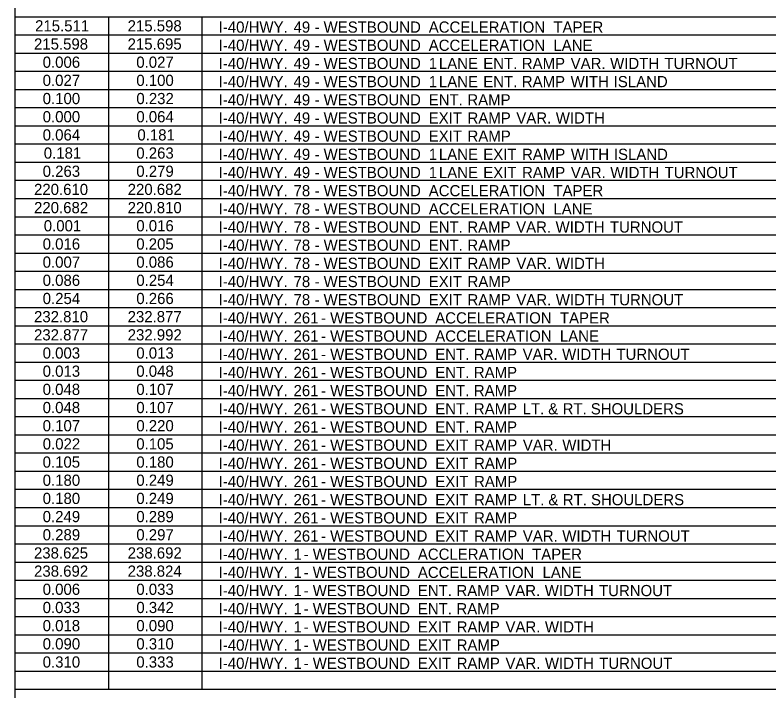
# Model space of a CAD drawing. Extents: x 2261867 to 2275370, y -3124789 to -3122260.
# Drawn here: x 2269400.2 to 2269764, y -3124228.5 to -3123902.3 of the extents above; entities that cross this region are included whole.
import ezdxf

# ---------------------------------------------------------------- set-up
doc = ezdxf.new("R2010")
doc.units = 0
doc.layers.add('Default', color=7, linetype='Continuous')

msp = doc.modelspace()

# ---------------------------------------------------------------- linework, layer by layer
at = {"layer": 'Default'}
for p, q in [((2269400.16, -3124701.59), (2269400.16, -3123657.37)), ((2269400.16, -3124701.59), (2269400.16, -3123657.37)), ((2269400.16, -3123903.07), (2270414.11, -3123903.07)), ((2269445.35, -3124218.97), (2269445.35, -3123903.07)), ((2269445.35, -3124227.74), (2269445.35, -3123903.07)), ((2269490.54, -3124210.19), (2269490.54, -3123903.07)), ((2269490.54, -3124227.74), (2269490.54, -3123903.07)), ((2269400.16, -3123911.84), (2270414.11, -3123911.84)), ((2269400.16, -3123920.62), (2270414.11, -3123920.62)), ((2269400.16, -3123929.39), (2270414.11, -3123929.39)), ((2269400.16, -3123938.17), (2270414.11, -3123938.17)), ((2269400.16, -3123946.94), (2270414.11, -3123946.94)), ((2269400.16, -3123955.72), (2270414.11, -3123955.72)), ((2269400.16, -3123964.49), (2270414.11, -3123964.49)), ((2269400.16, -3123973.27), (2270414.11, -3123973.27)), ((2269400.16, -3123982.04), (2270414.11, -3123982.04)), ((2269400.16, -3123990.82), (2270414.11, -3123990.82)), ((2269400.16, -3123999.59), (2270414.11, -3123999.59)), ((2269400.16, -3124008.37), (2270414.11, -3124008.37)), ((2269400.16, -3124017.14), (2270414.11, -3124017.14)), ((2269400.16, -3124025.92), (2270414.11, -3124025.92)), ((2269400.16, -3124034.69), (2270414.11, -3124034.69)), ((2269400.16, -3124043.47), (2270414.11, -3124043.47)), ((2269400.16, -3124052.24), (2270414.11, -3124052.24)), ((2269400.16, -3124061.02), (2270414.11, -3124061.02)), ((2269400.16, -3124069.79), (2270414.11, -3124069.79)), ((2269400.16, -3124078.57), (2270414.11, -3124078.57)), ((2269400.16, -3124087.34), (2270414.11, -3124087.34)), ((2269400.16, -3124096.12), (2270414.11, -3124096.12)), ((2269400.16, -3124104.89), (2270414.11, -3124104.89)), ((2269400.16, -3124113.67), (2270414.11, -3124113.67)), ((2269400.16, -3124122.44), (2270414.11, -3124122.44)), ((2269400.16, -3124131.22), (2270414.11, -3124131.22)), ((2269400.16, -3124139.99), (2270414.11, -3124139.99)), ((2269400.16, -3124148.77), (2270414.11, -3124148.77)), ((2269400.16, -3124157.54), (2270414.11, -3124157.54)), ((2269400.16, -3124166.32), (2270414.11, -3124166.32)), ((2269400.16, -3124175.09), (2270414.11, -3124175.09)), ((2269400.16, -3124183.87), (2270414.11, -3124183.87)), ((2269400.16, -3124192.64), (2270414.11, -3124192.64)), ((2269400.16, -3124201.42), (2270414.11, -3124201.42)), ((2269400.16, -3124210.19), (2270414.11, -3124210.19)), ((2269400.16, -3124218.97), (2269859.53, -3124218.97)), ((2269490.54, -3124227.74), (2269490.54, -3124218.97)), ((2269400.16, -3124227.74), (2270414.11, -3124227.74)), ((2269490.54, -3124227.74), (2269769.15, -3124227.74))]:
    msp.add_line(p, q, dxfattribs=at)

# ---------------------------------------------------------------- texts
for s, p in [('215.511', (2269409.82, -3123910.16)), ('215.598', (2269454.49, -3123910.16)), ('I-40/HWY.', (2269498.44, -3123910.76)), (' 49', (2269532.57, -3123910.76)), (' WESTBOUND', (2269547.09, -3123910.76)), (' ACCELERATION', (2269597.83, -3123910.76)), (' TAPER', (2269658.01, -3123910.76)), (' -', (2269542.72, -3123910.76)), ('215.598', (2269409.29, -3123918.93)), ('215.695', (2269454.47, -3123918.93)), ('I-40/HWY.', (2269498.44, -3123919.54)), (' 49', (2269532.57, -3123919.54)), (' WESTBOUND', (2269547.09, -3123919.54)), (' ACCELERATION', (2269597.83, -3123919.54)), (' LANE', (2269658.01, -3123919.54)), (' -', (2269542.72, -3123919.54)), ('0.006', (2269413.49, -3123927.71)), ('0.027', (2269458.68, -3123927.71)), ('I-40/HWY.', (2269498.44, -3123928.31)), (' 49', (2269532.57, -3123928.31)), (' -', (2269542.72, -3123928.31)), (' WESTBOUND', (2269547.09, -3123928.31)), (' 1', (2269597.83, -3123928.31)), (' LANE', (2269602.73, -3123928.31)), (' ENT.', (2269624.14, -3123928.31)), (' RAMP', (2269642.76, -3123928.31)), (' VAR.', (2269666.33, -3123928.31)), (' WIDTH', (2269685.38, -3123928.31)), (' TURNOUT', (2269711.59, -3123928.31)), ('0.027', (2269413.49, -3123936.48)), ('0.100', (2269458.69, -3123936.48)), ('I-40/HWY.', (2269498.44, -3123937.09)), (' 49', (2269532.57, -3123937.09)), (' WESTBOUND', (2269547.09, -3123937.09)), (' 1', (2269597.83, -3123937.09)), (' LANE', (2269602.73, -3123937.09)), (' ENT.', (2269624.14, -3123937.09)), (' RAMP', (2269642.76, -3123937.09)), (' WITH', (2269666.33, -3123937.09)), (' ISLAND', (2269687.09, -3123937.09)), (' -', (2269542.72, -3123937.09)), ('0.100', (2269413.5, -3123945.26)), ('0.232', (2269458.71, -3123945.26)), ('I-40/HWY.', (2269498.44, -3123945.86)), (' 49', (2269532.57, -3123945.86)), (' WESTBOUND', (2269547.09, -3123945.86)), (' ENT.', (2269597.83, -3123945.86)), (' RAMP', (2269616.46, -3123945.86)), (' -', (2269542.72, -3123945.86)), ('0.000', (2269413.5, -3123954.03)), ('0.064', (2269458.7, -3123954.03)), ('I-40/HWY.', (2269498.44, -3123954.64)), (' 49', (2269532.57, -3123954.64)), (' WESTBOUND', (2269547.09, -3123954.64)), (' EXIT', (2269597.83, -3123954.64)), (' RAMP', (2269616.55, -3123954.64)), (' VAR.', (2269640.11, -3123954.64)), (' WIDTH', (2269659.16, -3123954.64)), (' -', (2269542.72, -3123954.64)), ('0.064', (2269413.5, -3123962.81)), ('0.181', (2269459.21, -3123962.81)), ('I-40/HWY.', (2269498.44, -3123963.41)), (' 49', (2269532.57, -3123963.41)), (' WESTBOUND', (2269547.09, -3123963.41)), (' EXIT', (2269597.83, -3123963.41)), (' RAMP', (2269616.55, -3123963.41)), (' -', (2269542.72, -3123963.41)), ('0.181', (2269414.02, -3123971.58)), ('0.263', (2269458.68, -3123971.58)), ('I-40/HWY.', (2269498.44, -3123972.19)), (' 49', (2269532.57, -3123972.19)), (' WESTBOUND', (2269547.09, -3123972.19)), (' 1', (2269597.83, -3123972.19)), (' LANE', (2269602.73, -3123972.19)), (' EXIT', (2269624.14, -3123972.19)), (' RAMP', (2269642.85, -3123972.19)), (' WITH', (2269666.42, -3123972.19)), (' ISLAND', (2269687.18, -3123972.19)), (' -', (2269542.72, -3123972.19)), ('0.263', (2269413.49, -3123980.36)), ('0.279', (2269458.68, -3123980.36)), ('I-40/HWY.', (2269498.44, -3123980.96)), (' 49', (2269532.57, -3123980.96)), (' WESTBOUND', (2269547.09, -3123980.96)), (' 1', (2269597.83, -3123980.96)), (' LANE', (2269602.73, -3123980.96)), (' EXIT', (2269624.14, -3123980.96)), (' RAMP', (2269642.85, -3123980.96)), (' VAR.', (2269666.42, -3123980.96)), (' WIDTH', (2269685.47, -3123980.96)), (' TURNOUT', (2269711.68, -3123980.96)), (' -', (2269542.72, -3123980.96)), ('220.610', (2269409.31, -3123989.13)), ('220.682', (2269454.52, -3123989.13)), ('I-40/HWY.', (2269498.44, -3123989.74)), (' 78', (2269532.57, -3123989.74)), (' WESTBOUND', (2269547.09, -3123989.74)), (' ACCELERATION', (2269597.83, -3123989.74)), (' -', (2269542.72, -3123989.74)), (' TAPER', (2269658.01, -3123989.74)), ('220.682', (2269409.33, -3123997.91)), ('220.810', (2269454.5, -3123997.91)), ('I-40/HWY.', (2269498.44, -3123998.51)), (' 78', (2269532.57, -3123998.51)), (' WESTBOUND', (2269547.09, -3123998.51)), (' ACCELERATION', (2269597.83, -3123998.51)), (' LANE', (2269658.01, -3123998.51)), (' -', (2269542.72, -3123998.51)), ('0.001', (2269414.02, -3124006.68)), ('0.016', (2269458.68, -3124006.68)), ('I-40/HWY.', (2269498.44, -3124007.29)), (' 78', (2269532.57, -3124007.29)), (' WESTBOUND', (2269547.09, -3124007.29)), (' ENT.', (2269597.83, -3124007.29)), (' RAMP', (2269616.46, -3124007.29)), (' VAR.', (2269640.02, -3124007.29)), (' WIDTH', (2269659.07, -3124007.29)), (' TURNOUT', (2269685.28, -3124007.29)), (' -', (2269542.72, -3124007.29)), ('0.016', (2269413.49, -3124015.46)), ('0.205', (2269458.66, -3124015.46)), ('I-40/HWY.', (2269498.44, -3124016.06)), (' 78', (2269532.57, -3124016.06)), (' WESTBOUND', (2269547.09, -3124016.06)), (' ENT.', (2269597.83, -3124016.06)), (' RAMP', (2269616.46, -3124016.06)), (' -', (2269542.72, -3124016.06)), ('0.007', (2269413.49, -3124024.23)), ('0.086', (2269458.68, -3124024.23)), ('I-40/HWY.', (2269498.44, -3124024.84)), (' 78', (2269532.57, -3124024.84)), (' WESTBOUND', (2269547.09, -3124024.84)), (' EXIT', (2269597.83, -3124024.84)), (' RAMP', (2269616.55, -3124024.84)), (' VAR.', (2269640.11, -3124024.84)), (' WIDTH', (2269659.16, -3124024.84)), (' -', (2269542.72, -3124024.84)), ('0.086', (2269413.49, -3124033.01)), ('0.254', (2269458.7, -3124033.01)), ('I-40/HWY.', (2269498.44, -3124033.61)), (' 78', (2269532.57, -3124033.61)), (' -', (2269542.72, -3124033.61)), (' WESTBOUND', (2269547.09, -3124033.61)), (' EXIT', (2269597.83, -3124033.61)), (' RAMP', (2269616.55, -3124033.61)), ('0.254', (2269413.5, -3124041.78)), ('0.266', (2269458.68, -3124041.78)), ('I-40/HWY.', (2269498.44, -3124042.39)), (' 78', (2269532.57, -3124042.39)), (' WESTBOUND', (2269547.09, -3124042.39)), (' EXIT', (2269597.83, -3124042.39)), (' RAMP', (2269616.55, -3124042.39)), (' VAR.', (2269640.11, -3124042.39)), (' WIDTH', (2269659.16, -3124042.39)), (' TURNOUT', (2269685.37, -3124042.39)), (' -', (2269542.72, -3124042.39)), ('232.810', (2269409.31, -3124050.56)), ('232.877', (2269454.49, -3124050.56)), ('I-40/HWY.', (2269498.44, -3124051.16)), (' 261', (2269532.57, -3124051.16)), (' WESTBOUND', (2269550.23, -3124051.16)), (' ACCELERATION', (2269600.97, -3124051.16)), (' TAPER', (2269661.15, -3124051.16)), (' -', (2269545.86, -3124051.16)), ('232.877', (2269409.3, -3124059.33)), ('232.992', (2269454.52, -3124059.33)), ('I-40/HWY.', (2269498.44, -3124059.94)), (' 261', (2269532.57, -3124059.94)), (' WESTBOUND', (2269550.23, -3124059.94)), (' ACCELERATION', (2269600.97, -3124059.94)), (' LANE', (2269661.15, -3124059.94)), (' -', (2269545.86, -3124059.94)), ('0.003', (2269413.49, -3124068.11)), ('0.013', (2269458.68, -3124068.11)), ('I-40/HWY.', (2269498.44, -3124068.71)), (' 261', (2269532.57, -3124068.71)), (' WESTBOUND', (2269550.23, -3124068.71)), (' ENT.', (2269600.97, -3124068.71)), (' RAMP', (2269619.6, -3124068.71)), (' VAR.', (2269643.16, -3124068.71)), (' WIDTH', (2269662.21, -3124068.71)), (' TURNOUT', (2269688.42, -3124068.71)), (' -', (2269545.86, -3124068.71)), ('0.013', (2269413.49, -3124076.88)), ('0.048', (2269458.68, -3124076.88)), ('I-40/HWY.', (2269498.44, -3124077.49)), (' 261', (2269532.57, -3124077.49)), (' -', (2269545.86, -3124077.49)), (' WESTBOUND', (2269550.23, -3124077.49)), (' ENT.', (2269600.97, -3124077.49)), (' RAMP', (2269619.6, -3124077.49)), ('0.048', (2269413.49, -3124085.66)), ('0.107', (2269458.68, -3124085.66)), ('I-40/HWY.', (2269498.44, -3124086.26)), (' 261', (2269532.57, -3124086.26)), (' WESTBOUND', (2269550.23, -3124086.26)), (' ENT.', (2269600.97, -3124086.26)), (' RAMP', (2269619.6, -3124086.26)), (' -', (2269545.86, -3124086.26)), ('0.048', (2269413.49, -3124094.43)), ('0.107', (2269458.68, -3124094.43)), ('I-40/HWY.', (2269498.44, -3124095.04)), (' 261', (2269532.57, -3124095.04)), (' WESTBOUND', (2269550.23, -3124095.04)), (' ENT.', (2269600.97, -3124095.04)), (' RAMP', (2269619.6, -3124095.04)), (' LT.', (2269643.16, -3124095.04)), (' &', (2269655.5, -3124095.04)), (' RT.', (2269662.45, -3124095.04)), (' SHOULDERS', (2269676.04, -3124095.04)), (' -', (2269545.86, -3124095.04)), ('0.107', (2269413.49, -3124103.21)), ('0.220', (2269458.69, -3124103.21)), ('I-40/HWY.', (2269498.44, -3124103.81)), (' 261', (2269532.57, -3124103.81)), (' WESTBOUND', (2269550.23, -3124103.81)), (' ENT.', (2269600.97, -3124103.81)), (' RAMP', (2269619.6, -3124103.81)), (' -', (2269545.86, -3124103.81)), ('0.022', (2269413.52, -3124111.98)), ('0.105', (2269458.66, -3124111.98)), ('I-40/HWY.', (2269498.44, -3124112.59)), (' 261', (2269532.57, -3124112.59)), (' WESTBOUND', (2269550.23, -3124112.59)), (' EXIT', (2269600.97, -3124112.59)), (' RAMP', (2269619.69, -3124112.59)), (' VAR.', (2269643.25, -3124112.59)), (' WIDTH', (2269662.3, -3124112.59)), (' -', (2269545.86, -3124112.59)), ('0.105', (2269413.47, -3124120.76)), ('0.180', (2269458.69, -3124120.76)), ('I-40/HWY.', (2269498.44, -3124121.36)), (' 261', (2269532.57, -3124121.36)), (' WESTBOUND', (2269550.23, -3124121.36)), (' EXIT', (2269600.97, -3124121.36)), (' RAMP', (2269619.69, -3124121.36)), (' -', (2269545.86, -3124121.36)), ('0.180', (2269413.5, -3124129.53)), ('0.249', (2269458.68, -3124129.53)), ('I-40/HWY.', (2269498.44, -3124130.14)), (' 261', (2269532.57, -3124130.14)), (' WESTBOUND', (2269550.23, -3124130.14)), (' EXIT', (2269600.97, -3124130.14)), (' RAMP', (2269619.69, -3124130.14)), (' -', (2269545.86, -3124130.14)), ('0.180', (2269413.5, -3124138.31)), ('0.249', (2269458.68, -3124138.31)), ('I-40/HWY.', (2269498.44, -3124138.91)), (' 261', (2269532.57, -3124138.91)), (' WESTBOUND', (2269550.23, -3124138.91)), (' EXIT', (2269600.97, -3124138.91)), (' RAMP', (2269619.69, -3124138.91)), (' LT.', (2269643.25, -3124138.91)), (' &', (2269655.59, -3124138.91)), (' RT.', (2269662.54, -3124138.91)), (' SHOULDERS', (2269676.14, -3124138.91)), (' -', (2269545.86, -3124138.91)), ('0.249', (2269413.49, -3124147.08)), ('0.289', (2269458.68, -3124147.08)), ('I-40/HWY.', (2269498.44, -3124147.69)), (' 261', (2269532.57, -3124147.69)), (' WESTBOUND', (2269550.23, -3124147.69)), (' EXIT', (2269600.97, -3124147.69)), (' RAMP', (2269619.69, -3124147.69)), (' -', (2269545.86, -3124147.69)), ('0.289', (2269413.49, -3124155.86)), ('0.297', (2269458.68, -3124155.86)), ('I-40/HWY.', (2269498.44, -3124156.46)), (' 261', (2269532.57, -3124156.46)), (' WESTBOUND', (2269550.23, -3124156.46)), (' EXIT', (2269600.97, -3124156.46)), (' RAMP', (2269619.69, -3124156.46)), (' VAR.', (2269643.25, -3124156.46)), (' WIDTH', (2269662.3, -3124156.46)), (' TURNOUT', (2269688.51, -3124156.46)), (' -', (2269545.86, -3124156.46)), ('238.625', (2269409.28, -3124164.63)), ('238.692', (2269454.52, -3124164.63)), ('I-40/HWY.', (2269498.44, -3124165.24)), (' 1', (2269532.57, -3124165.24)), (' WESTBOUND', (2269541.84, -3124165.24)), (' ACCLERATION', (2269592.58, -3124165.24)), (' TAPER', (2269647.73, -3124165.24)), (' -', (2269537.47, -3124165.24)), ('238.692', (2269409.33, -3124173.41)), ('238.824', (2269454.5, -3124173.41)), ('I-40/HWY.', (2269498.44, -3124174.01)), (' 1', (2269532.57, -3124174.01)), (' WESTBOUND', (2269541.84, -3124174.01)), (' ACCELERATION', (2269592.58, -3124174.01)), (' LANE', (2269652.76, -3124174.01)), (' -', (2269537.47, -3124174.01)), ('0.006', (2269413.49, -3124182.18)), ('0.033', (2269458.68, -3124182.18)), ('I-40/HWY.', (2269498.44, -3124182.79)), (' 1', (2269532.57, -3124182.79)), (' -', (2269537.47, -3124182.79)), (' WESTBOUND', (2269541.84, -3124182.79)), (' ENT.', (2269592.58, -3124182.79)), (' RAMP', (2269611.21, -3124182.79)), (' VAR.', (2269634.78, -3124182.79)), (' WIDTH', (2269653.82, -3124182.79)), (' TURNOUT', (2269680.03, -3124182.79)), ('0.033', (2269413.49, -3124190.96)), ('0.342', (2269458.71, -3124190.96)), ('I-40/HWY.', (2269498.44, -3124191.56)), (' 1', (2269532.57, -3124191.56)), (' WESTBOUND', (2269541.84, -3124191.56)), (' ENT.', (2269592.58, -3124191.56)), (' RAMP', (2269611.21, -3124191.56)), (' -', (2269537.47, -3124191.56)), ('0.018', (2269413.49, -3124199.73)), ('0.090', (2269458.69, -3124199.73)), ('I-40/HWY.', (2269498.44, -3124200.34)), (' 1', (2269532.57, -3124200.34)), (' WESTBOUND', (2269541.84, -3124200.34)), (' EXIT', (2269592.58, -3124200.34)), (' RAMP', (2269611.3, -3124200.34)), (' VAR.', (2269634.87, -3124200.34)), (' WIDTH', (2269653.91, -3124200.34)), (' -', (2269537.47, -3124200.34)), ('0.090', (2269413.5, -3124208.51)), ('0.310', (2269458.69, -3124208.51)), ('I-40/HWY.', (2269498.44, -3124209.11)), (' 1', (2269532.57, -3124209.11)), (' WESTBOUND', (2269541.84, -3124209.11)), (' EXIT', (2269592.58, -3124209.11)), (' RAMP', (2269611.3, -3124209.11)), (' -', (2269537.47, -3124209.11)), ('0.310', (2269413.5, -3124217.28)), ('0.333', (2269458.68, -3124217.28)), ('I-40/HWY.', (2269498.44, -3124217.89)), (' 1', (2269532.57, -3124217.89)), (' WESTBOUND', (2269541.84, -3124217.89)), (' EXIT', (2269592.58, -3124217.89)), (' RAMP', (2269611.3, -3124217.89)), (' VAR.', (2269634.87, -3124217.89)), (' WIDTH', (2269653.91, -3124217.89)), (' TURNOUT', (2269680.12, -3124217.89)), (' -', (2269537.47, -3124217.89))]:
    msp.add_text(s, height=5.4, dxfattribs=at).set_placement(p)

doc.saveas('drawing.dxf')
